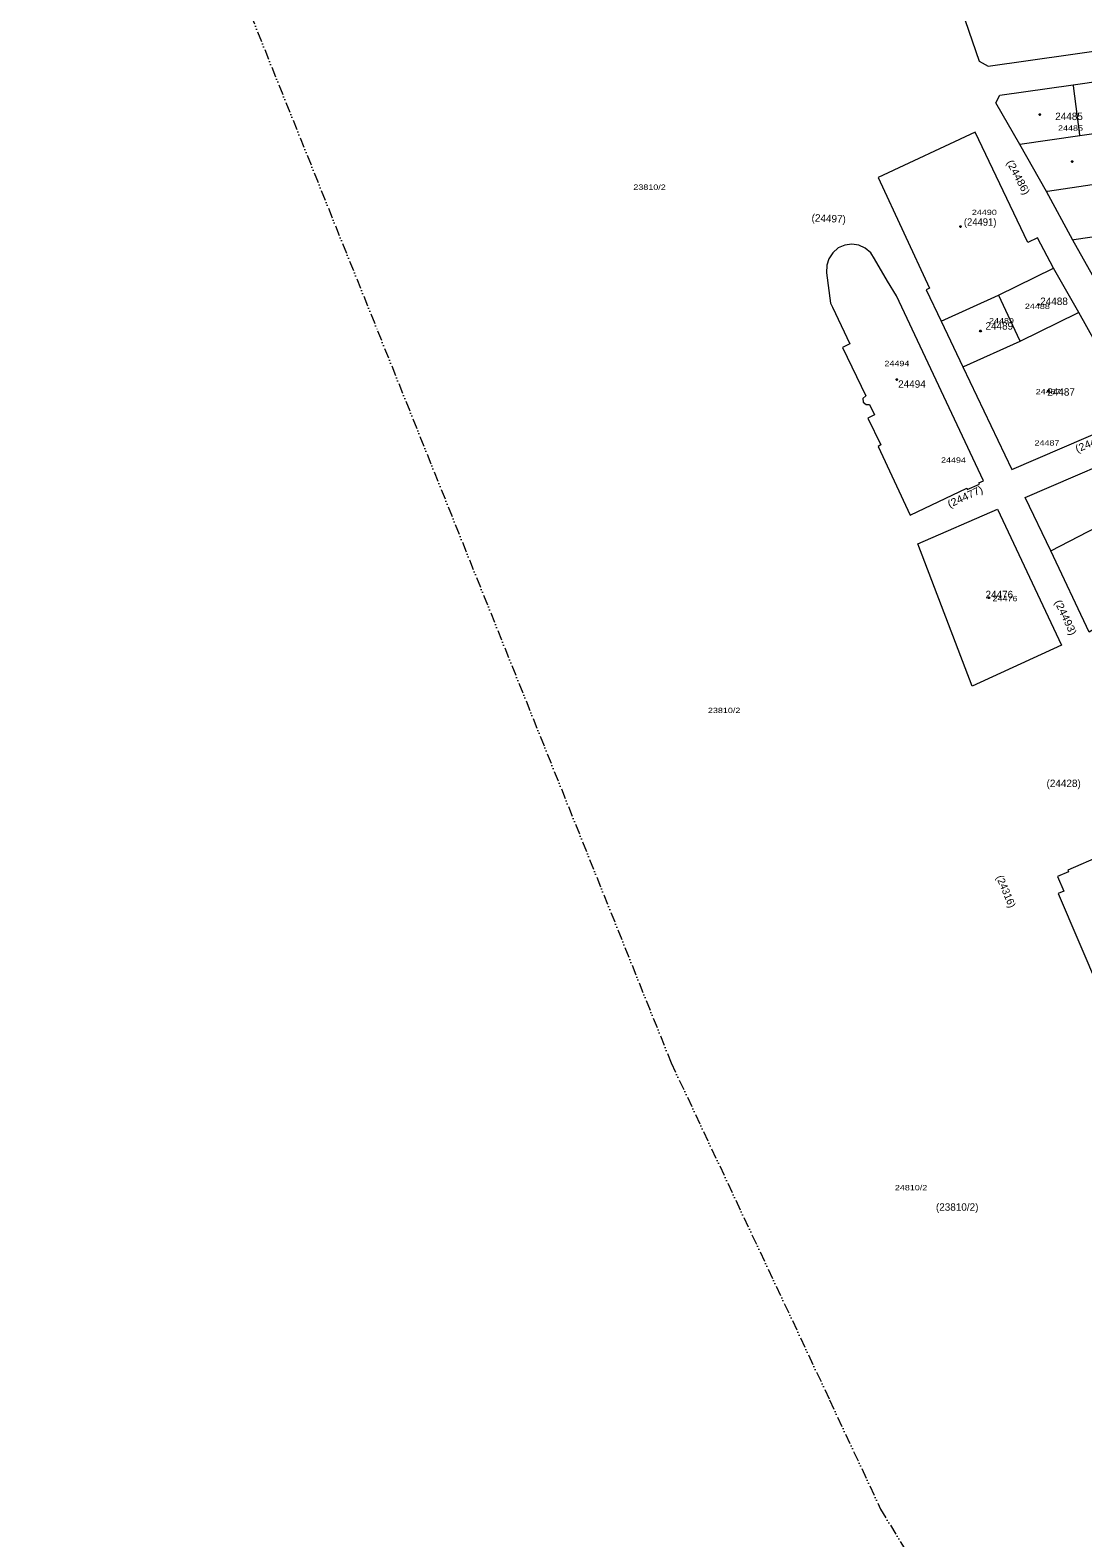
# Model space of a CAD drawing. Extents: x 649608 to 651081, y 237980 to 241202.
# Drawn here: x 649608 to 650118, y 238710 to 239441 of the extents above; entities that cross this region are included whole.
import ezdxf

# ---------------------------------------------------------------- set-up
doc = ezdxf.new("R2010")
doc.units = 0
doc.header["$PDMODE"] = 32
doc.header["$PDSIZE"] = 0.5
doc.linetypes.add('DASH_DOUBLE_DOT', pattern=[9.2, 5, -1.2, 0.3, -1.2, 0.3, -1.2])
for name, color, linetype in [('19', 7, 'Continuous'), ('20', 7, 'Continuous'), ('6', 7, 'Continuous')]:
    doc.layers.add(name, color=color, linetype=linetype)
for name, color, linetype, lineweight in [('3', 7, 'Continuous', 13), ('39', 7, 'Continuous', 13), ('5', 7, 'Continuous', 13), ('52', 7, 'DASH_DOUBLE_DOT', 13)]:
    doc.layers.add(name, color=color, linetype=linetype, lineweight=lineweight)

msp = doc.modelspace()

# ---------------------------------------------------------------- linework, layer by layer
at = {"layer": '3'}
msp.add_line((650049.753, 239299.912), (650060.24, 239277.75), dxfattribs=at)
for points in [[(650046.003, 239490.267), (650068.149, 239425.852), (650072.472, 239423.448), (650132.999, 239431.986)], [(650076.272, 239405.643), (650078.266, 239409.41), (650113.744, 239414.433), (650128.237, 239416.516)], [(650171.539, 239385.019), (650183.987, 239304.061), (650183.875, 239299.271), (650180.56, 239296.372), (650157.812, 239279.426), (650152.812, 239276.665), (650149.116, 239277.45), (650145.625, 239281.94), (650113.519, 239339.195), (650100.824, 239362.641), (650087.843, 239385.509), (650076.272, 239405.643)], [(650070.262, 239222.616), (650028.066, 239312.102), (650023.829, 239319.294), (650017.473, 239330.131), (650015.707, 239333.069), (650012.991, 239335.258), (650009.811, 239336.744), (650006.445, 239337.223), (650003.072, 239336.694), (649999.846, 239335.358), (649997.328, 239333.032), (649995.368, 239330.173), (649994.324, 239326.954), (649994.247, 239323.35), (649996.108, 239308.689), (649997.192, 239306.74), (650005.489, 239288.955), (650001.928, 239287.217), (650013.197, 239263.763), (650011.886, 239262.411), (650012.052, 239260.671), (650013.371, 239259.501), (650015.005, 239259.539), (650017.522, 239254.554), (650014.294, 239252.915), (650020.481, 239239.91), (650019.251, 239239.188), (650034.815, 239205.945)], [(650049.753, 239299.912), (650077.473, 239312.543), (650104.179, 239325.641)], [(650060.24, 239277.75), (650083.957, 239228.008), (650144.359, 239254.095), (650116.406, 239304.12), (650104.179, 239325.641)], [(650090.509, 239214.51), (650152.062, 239240.917), (650165.182, 239223.066), (650176.051, 239208.081)], [(650034.815, 239205.945), (650062.246, 239218.921), (650062.421, 239218.365), (650068.361, 239220.917), (650068.008, 239221.524), (650070.262, 239222.616)], [(650155.215, 239170.116), (650121.458, 239149.195), (650102.881, 239188.672), (650090.509, 239214.51)], [(650175.64, 238984.959), (650163.177, 239014.357), (650164.099, 239014.754), (650162.193, 239019.433), (650161.093, 239019.088), (650151.078, 239042.463), (650149.029, 239041.672), (650143.677, 239053.337), (650133.483, 239049.027), (650135.139, 239045.081), (650127.072, 239041.916), (650127.448, 239040.955), (650111.131, 239033.869), (650111.508, 239033.059), (650106.205, 239030.78), (650109.243, 239023.797), (650106.374, 239022.533), (650136.506, 238952.341)]]:
    msp.add_lwpolyline(points, dxfattribs=at)
msp.add_lwpolyline([(650038.51, 239192.065), (650076.985, 239208.79), (650108.032, 239142.919), (650064.834, 239123.003)], close=True, dxfattribs=at)
at = {"layer": '39'}
msp.add_lwpolyline([(650104.179, 239325.641), (650096.481, 239340.276), (650091.688, 239338.09), (650066.233, 239391.508), (650019.191, 239369.534), (650044.189, 239315.945), (650042.558, 239315.095), (650049.753, 239299.912)], dxfattribs=at)
at = {"layer": '5'}
msp.add_line((650102.881, 239188.672), (650137.202, 239206.437), dxfattribs=at)
for points in [[(650116.932, 239389.749), (650116.867, 239390.249), (650113.809, 239413.933), (650113.744, 239414.433)], [(650131.91, 239391.803), (650131.41, 239391.734), (650116.932, 239389.749), (650087.843, 239385.509)], [(650135.357, 239367.722), (650140.827, 239368.411), (650143.963, 239343.627), (650114.019, 239339.268), (650113.519, 239339.195)], [(650135.357, 239367.722), (650134.857, 239367.648), (650101.324, 239362.715), (650100.824, 239362.641)], [(650077.473, 239312.543), (650087.745, 239290.673), (650087.98, 239290.173)], [(650087.98, 239290.173), (650115.906, 239303.875), (650116.406, 239304.12)], [(650060.24, 239277.75), (650060.74, 239277.974), (650087.98, 239290.173)]]:
    msp.add_lwpolyline(points, dxfattribs=at)
at = {"layer": '52'}
msp.add_lwpolyline([(649701.481, 241202.319), (649640.936, 240904.262), (649608.393, 240352.424), (649614.771, 240009.578), (649631.5, 239894.49), (649662.347, 239679.564), (649715.192, 239448.546), (649776.71, 239295.263), (649918.979, 238940.568), (649995.713, 238777.318), (650020.382, 238724.355), (650126.69, 238550.145), (650295.37, 238327.169), (650466.153, 238100.489), (650557.889, 237992.529), (650568.158, 237979.989)], dxfattribs=at)
at = {"layer": '6'}
for p in [(650097.572, 239399.971), (650113.204, 239377.222), (650059.181, 239345.71), (650096.952, 239307.907), (650068.826, 239295.146), (650028.305, 239271.584), (650101.741, 239266.064), (650072.843, 239165.896)]:
    msp.add_point(p, dxfattribs=at)

# ---------------------------------------------------------------- texts
at = {"layer": '19'}
for s, p in [('24485', (650105.021, 239397.32)), ('24488', (650097.753, 239307.731)), ('24489', (650071.247, 239295.786)), ('24494', (650028.924, 239267.63)), ('24487', (650101.172, 239263.791)), ('24476', (650071.248, 239165.67)), ('(24428)', (650100.819, 239074.195)), ('(23810/2)', (650047.225, 238868.916))]:
    msp.add_text(s, height=3.6, dxfattribs=at).set_placement(p)
at = {"layer": '19', "width": 1.1}
for s, rotation, p in [('(24486)', 297.791, (650081.29, 239376.868)), ('(24478)', 23.35, (650115.688, 239236.11)), ('(24477)', 24.905, (650053.863, 239209.406)), ('(24493)', 295.287, (650104.597, 239163.858))]:
    msp.add_text(s, height=3.6, rotation=rotation, dxfattribs=at).set_placement(p)
at = {"layer": '19'}
for s, rotation, p in [('(24497)', 357.288, (649986.921, 239348.245)), ('(24316)', 292.936, (650076.309, 239030.575))]:
    msp.add_text(s, height=3.6, rotation=rotation, dxfattribs=at).set_placement(p)
at = {"layer": '19', "width": 0.95}
msp.add_text('(24491)', height=3.6, dxfattribs=at).set_placement((650060.776, 239346.15))
at = {"layer": '20', "width": 1.25}
for s, p in [('24485', (650106.396, 239392.145)), ('23810/2', (649900.63, 239363.514)), ('24490', (650064.64, 239351.31)), ('24488', (650090.319, 239305.808)), ('24489', (650072.952, 239298.788)), ('24494', (650022.268, 239278.086)), ('24487', (650095.56, 239264.446)), ('24487', (650094.976, 239239.596)), ('24494', (650049.683, 239231.303)), ('24476', (650074.627, 239164.204)), ('23810/2', (649936.768, 239110.022)), ('24810/2', (650027.328, 238878.799))]:
    msp.add_text(s, height=2.6, dxfattribs=at).set_placement(p)

doc.saveas('drawing.dxf')
